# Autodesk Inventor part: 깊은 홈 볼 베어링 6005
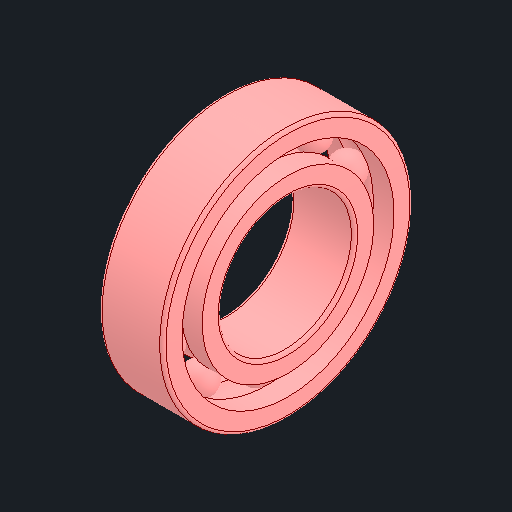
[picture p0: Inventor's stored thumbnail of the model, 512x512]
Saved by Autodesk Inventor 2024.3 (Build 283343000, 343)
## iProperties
Created: 2025-07
Part Number: 깊은 홈 볼 베어링 6005
Material: 강철, 연강
Description: 깊은 그루브 볼 베어링
Document SubType Name: Modeling
Designer: user
Density: 7.85 g/cm^3
Appearance: 기본값
Author: jhkim
Sending System: Autodesk Inventor 2026
Preprocessor: ST-DEVELOPER v20.1
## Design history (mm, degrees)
feature "Solid1"
feature "Solid1:1"
feature "Solid1:2"
feature "Solid1:3"
feature "Solid1:4"
feature "Solid1:5"
feature "Solid1:6"
feature "Solid1:7"
feature "Solid1:8"
feature "Solid1:9"
feature "Solid1:10"
feature "Solid1:11"
node "솔리드1"
node "솔리드2"
node "솔리드3"
node "솔리드4"
node "솔리드5"
node "솔리드6"
node "솔리드7"
node "솔리드8"
node "솔리드9"
node "솔리드10"
node "솔리드11"
node "솔리드12"
